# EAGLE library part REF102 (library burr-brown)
10.0V Precision Voltage Reference
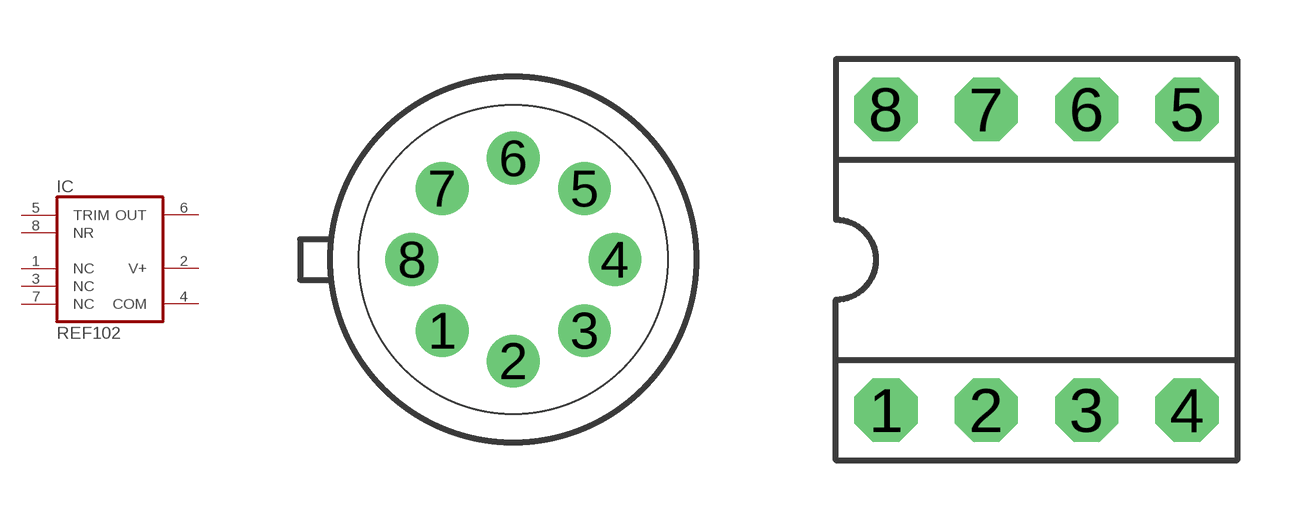
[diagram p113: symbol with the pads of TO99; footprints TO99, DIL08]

Designator prefix IC

## REF102M (OC_FARNELL: unknown; OC_NEWARK: unknown)  [TO99]
1  NC  nc
2  V+  pwr
3  NC  nc
4  COM  pwr
5  TRIM  pas
6  OUT  in
7  NC  nc
8  NR  pas

## REF102P (MF: TEXAS INSTRUMENTS; MPN: REF102AP; OC_FARNELL: 1097429; OC_NEWARK: 10M5244)  [DIL08]
Pads as for TO99

## REF102U (MF: TEXAS INSTRUMENTS; MPN: REF102AU; OC_FARNELL: 1212344; OC_NEWARK: 04M4600)  [SO08]
Pads as for TO99

## Footprint TO99 (pad centres in mm)
Metal can Package
drill 0.813 round: 1 -1.778,-1.778; 2 0,-2.54; 3 1.778,-1.778; 4 2.54,0; 5 1.778,1.778; 6 0,2.54; 7 -1.778,1.778; 8 -2.54,0

## Footprint DIL08 (pad centres in mm)
Dual In Line
drill 0.813 pad 1.6 octagon: 1 -3.81,-3.81; 2 -1.27,-3.81; 3 1.27,-3.81; 4 3.81,-3.81; 5 3.81,3.81; 6 1.27,3.81; 7 -1.27,3.81; 8 -3.81,3.81

## Footprint SO08 (pad centres in mm)
Small Outline Package
smd 0.61 x 2.21: 1 -1.905,-2.616; 2 -0.635,-2.616; 3 0.635,-2.616; 4 1.905,-2.616; 5 1.905,2.616; 6 0.635,2.616; 7 -0.635,2.616; 8 -1.905,2.616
